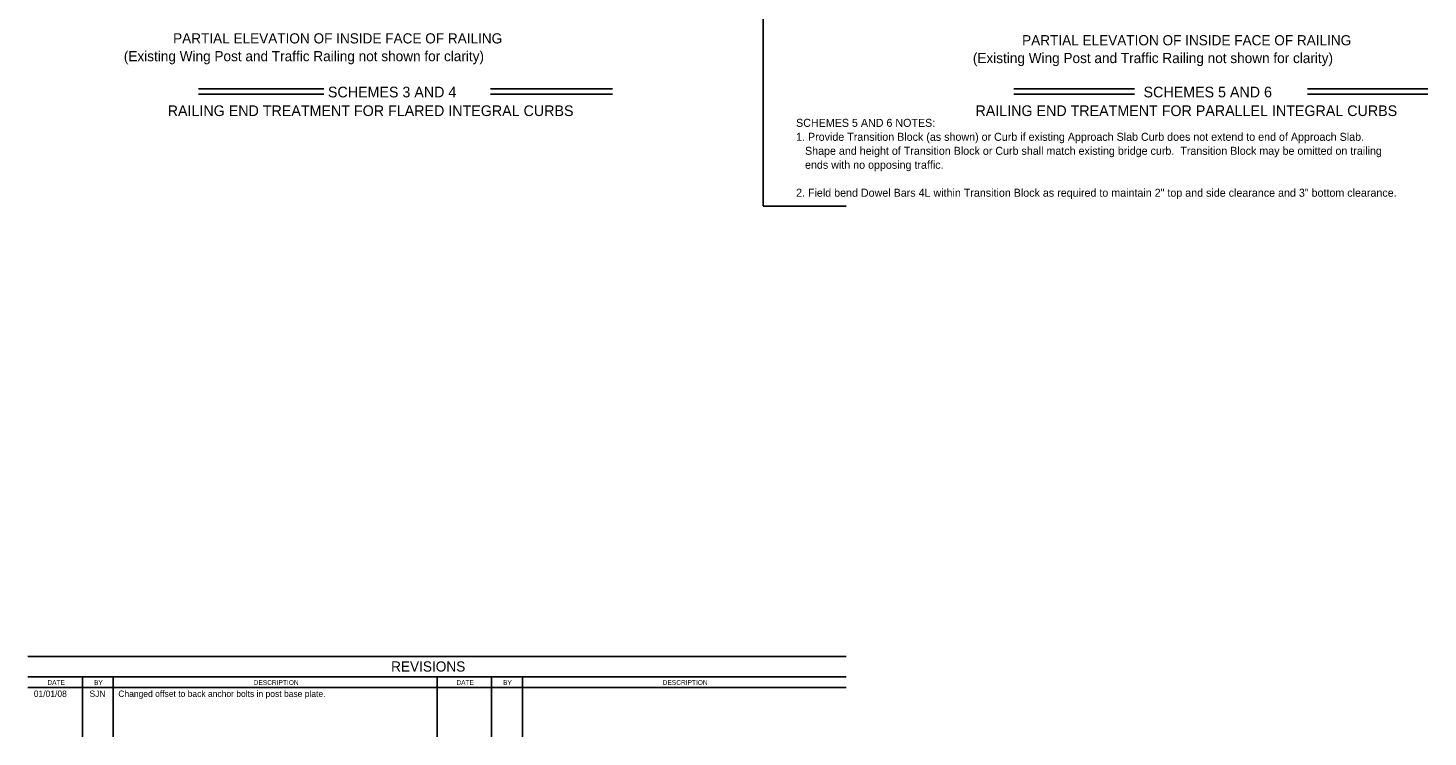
# Model space of a CAD drawing. Extents: x 21587 to 21656.3, y 56114 to 56157.2.
# Drawn here: x 21586.98 to 21622.25, y 56113.95 to 56131.8 of the extents above; entities that cross this region are included whole.
import ezdxf

# ---------------------------------------------------------------- set-up
doc = ezdxf.new("R2010")
doc.units = 0
for name, color, linetype in [('Border', 7, 'Continuous'), ('PlotBorder_dp', 7, 'Continuous'), ('SheetBorder_dp', 7, 'Continuous')]:
    doc.layers.add(name, color=color, linetype=linetype)

msp = doc.modelspace()

# ---------------------------------------------------------------- linework, layer by layer
at = {"layer": 'Border'}
for p, q in [((21607.59, 56115.981), (21586.978, 56115.981)), ((21607.59, 56115.466), (21586.978, 56115.466)), ((21588.355, 56115.466), (21588.355, 56113.951)), ((21589.128, 56115.466), (21589.128, 56113.951)), ((21597.284, 56115.466), (21597.284, 56113.951)), ((21598.661, 56115.466), (21598.661, 56113.951)), ((21599.434, 56115.466), (21599.434, 56113.951)), ((21586.978, 56115.193), (21607.59, 56115.193))]:
    msp.add_line(p, q, dxfattribs=at)
at = {"layer": 'PlotBorder_dp'}
for p, q in [((21605.502, 56153.256), (21605.502, 56127.327)), ((21594.432, 56130.27), (21591.272, 56130.27)), ((21598.629, 56130.27), (21601.705, 56130.27)), ((21614.863, 56130.27), (21611.821, 56130.27)), ((21619.217, 56130.27), (21622.254, 56130.27)), ((21594.432, 56130.137), (21591.272, 56130.137)), ((21598.629, 56130.137), (21601.705, 56130.137)), ((21614.863, 56130.137), (21611.821, 56130.137)), ((21619.217, 56130.137), (21622.254, 56130.137)), ((21607.59, 56127.317), (21605.502, 56127.317))]:
    msp.add_line(p, q, dxfattribs=at)

# ---------------------------------------------------------------- texts
for s, height, p in [('PARTIAL ELEVATION OF INSIDE FACE OF RAILING', 0.256, (21590.634, 56131.415)), ('PARTIAL ELEVATION OF INSIDE FACE OF RAILING', 0.256, (21612.027, 56131.368)), ('(Existing Wing Post and Traffic Railing not shown for clarity)', 0.256, (21589.393, 56130.967)), ('(Existing Wing Post and Traffic Railing not shown for clarity)', 0.256, (21610.786, 56130.92)), ('SCHEMES 3 AND 4', 0.2688, (21594.535, 56130.057)), ('SCHEMES 5 AND 6', 0.2688, (21615.087, 56130.057)), ('RAILING END TREATMENT FOR FLARED INTEGRAL CURBS', 0.2688, (21590.498, 56129.587)), ('RAILING END TREATMENT FOR PARALLEL INTEGRAL CURBS', 0.2688, (21610.852, 56129.587)), ('SCHEMES 5 AND 6 NOTES:', 0.2016, (21606.332, 56129.315)), ('1. Provide Transition Block (as shown) or Curb if existing Approach Slab Curb does not extend to end of Approach Slab.  ', 0.2016, (21606.332, 56128.963)), ('   Shape and height of Transition Block or Curb shall match existing bridge curb.  Transition Block may be omitted on trailing ', 0.2016, (21606.332, 56128.611)), ('   ends with no opposing traffic.', 0.2016, (21606.332, 56128.259)), ('2. Field bend Dowel Bars 4L within Transition Block as required to maintain 2" top and side clearance and 3" bottom clearance.', 0.2016, (21606.332, 56127.555))]:
    msp.add_text(s, height=height, dxfattribs=at).set_placement(p)
at = {"layer": 'SheetBorder_dp'}
for s, height, p in [('REVISIONS', 0.2567, (21596.127, 56115.598)), ('01/01/08', 0.16, (21587.124, 56114.96)), ('SJN', 0.16, (21588.527, 56114.96)), ('BY', 0.1201, (21588.642, 56115.263)), ('Changed offset to back anchor bolts in post base plate.', 0.16, (21589.253, 56114.96)), ('BY', 0.1201, (21598.948, 56115.263))]:
    msp.add_text(s, height=height, dxfattribs=at).set_placement(p)
for s, height, rotation, p in [('DATE', 0.1196, 359.8693, (21587.467, 56115.264)), ('DESCRIPTION', 0.12007, 0.0498, (21592.664, 56115.263)), ('DATE', 0.1196, 359.8693, (21597.773, 56115.264)), ('DESCRIPTION', 0.12007, 0.0498, (21602.971, 56115.263))]:
    msp.add_text(s, height=height, rotation=rotation, dxfattribs=at).set_placement(p)

doc.saveas('drawing.dxf')
